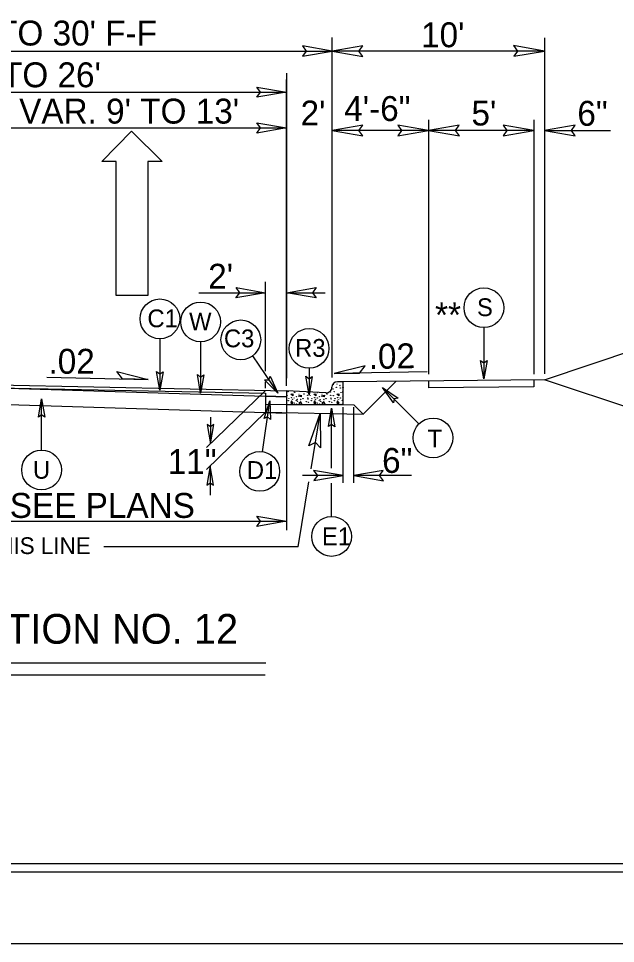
# Model space of a CAD drawing. Extents: x 958711 to 962106, y 831169 to 840840.
# Drawn here: x 959536.1 to 959723.1, y 834842.4 to 835132 of the extents above; entities that cross this region are included whole.
import ezdxf

# ---------------------------------------------------------------- set-up
doc = ezdxf.new("R2010")
doc.units = 0
for name, color, linetype in [('Old_Level_1', 7, 'Continuous'), ('Old_Level_11', 7, 'Continuous'), ('Old_Level_3', 7, 'Continuous'), ('Prop Dimension Text', 7, 'Continuous'), ('Prop Lane Arrow CELL', 7, 'Continuous'), ('Sheet Plot Border Inside CELL', 7, 'Continuous'), ('Sheet Plot Border Outside CELL', 7, 'Continuous'), ('Sheet Typical CELL', 7, 'Continuous'), ('Typical ID Circle CELL', 7, 'Continuous'), ('Typical Terminator CELL', 7, 'Continuous'), ('Typical Text ID Circle CELL', 7, 'Continuous')]:
    doc.layers.add(name, color=color, linetype=linetype)

# ---------------------------------------------------------------- blocks, each defined once
blk = doc.blocks.new('Lane Arrow Through')
at = {"layer": 'Prop Lane Arrow CELL'}
for p, q in [((-3.15, 1.6), (-3.15, 3.1)), ((-3.15, 3.1), (0, 0)), ((-17.15, 1.6), (-3.15, 1.6)), ((-17.15, -1.7), (-17.15, 1.6)), ((0, 0), (-3.15, -3.2)), ((-3.15, -1.7), (-17.15, -1.7)), ((-3.15, -3.2), (-3.15, -1.7))]:
    blk.add_line(p, q, dxfattribs=at)

msp = doc.modelspace()

# ---------------------------------------------------------------- linework, layer by layer
at = {"layer": 'Old_Level_1'}
for p, q in [((959634.32, 835019.58), (959634.32, 835126.05)), ((959700.88, 835126), (959700.88, 835020.79)), ((959418.82, 835121.85), (959634.32, 835121.85)), ((959700.88, 835121.85), (959634.32, 835121.85)), ((959620.02, 835114.91), (959620.02, 835019.44)), ((959620.02, 835016.99), (959620.02, 835112.9)), ((959433.06, 835108.99), (959620.02, 835108.99)), ((959664.55, 835100.29), (959664.55, 835020.64)), ((959697.57, 835100.29), (959697.57, 835020.72)), ((959526.54, 835097.75), (959620.02, 835097.75)), ((959664.55, 835096.97), (959634.32, 835096.97)), ((959697.57, 835096.97), (959664.55, 835096.97)), ((959700.88, 835096.97), (959721.54, 835096.97)), ((959613.48, 835021.65), (959613.48, 835049.62)), ((959592.56, 835046.17), (959613.48, 835046.17)), ((959620.08, 835046.17), (959632.2, 835046.17)), ((959700.88, 835018.94), (959778.06, 835044.67)), ((959664.16, 835021.44), (959634.95, 835020.85)), ((959526.54, 835017.35), (959620.02, 835015.46)), ((959544.97, 835019.69), (959576.67, 835019.05)), ((959613.48, 835016.33), (959613.48, 835018.23)), ((959700.88, 835018.94), (959637.83, 835018.31)), ((959644.1, 835008.14), (959654.42, 835018.47)), ((959664.55, 835018.57), (959664.55, 835016.39)), ((959697.57, 835018.9), (959697.57, 835016.72)), ((959778.06, 834993.21), (959700.88, 835018.94)), ((959526.53, 835016.48), (959613.48, 835014.73)), ((959526.57, 835016.48), (959620.02, 835013.55)), ((959613.48, 835015.59), (959595.01, 834997.66)), ((959613.48, 835014.73), (959613.48, 835008.76)), ((959697.57, 835016.72), (959664.55, 835016.39)), ((959526.54, 835011.35), (959620.02, 835008.42)), ((959613.48, 835013.86), (959620.02, 835013.73)), ((959613.48, 835011.31), (959620.02, 835011.18)), ((959620.02, 835013.55), (959620.02, 835008.42)), ((959637.83, 835011.18), (959641.13, 835011.11)), ((959641.13, 835011.11), (959644.1, 835008.14)), ((959613.46, 835008.76), (959594.98, 834990.84)), ((959613.46, 835008.76), (959644.1, 835008.14)), ((959620.02, 835008.23), (959620.02, 834971.78)), ((959627.75, 834990.99), (959630.62, 835008.4)), ((959637.83, 834986.62), (959637.83, 835010.38)), ((959641.13, 834986.62), (959641.13, 835010.38)), ((959596.22, 835007.2), (959596.22, 834998.84)), ((959596.16, 834992.01), (959596.15, 834982.79)), ((959637.83, 834988.92), (959625.06, 834988.92)), ((959659.27, 834988.92), (959641.13, 834988.92)), ((959623.73, 834966.64), (959627.08, 834986.98)), ((959433.06, 834974.66), (959620.02, 834974.66)), ((959623.73, 834966.64), (959562.82, 834966.64)), ((959613.61, 834930.23), (959445.91, 834930.23)), ((959613.32, 834926.42), (959445.63, 834926.42))]:
    msp.add_line(p, q, dxfattribs=at)
msp.add_arc((959637.52, 835014.72), 0.309, 0, 90, dxfattribs=at)
at = {"layer": 'Old_Level_11'}
for p, q in [((959644.68, 835023.27), (959634.95, 835020.85)), ((959642.95, 835021.01), (959644.68, 835023.27)), ((959568.67, 835019.21), (959566.94, 835021.47)), ((959566.94, 835021.47), (959576.67, 835019.05)), ((959634.95, 835020.85), (959642.95, 835021.01)), ((959576.67, 835019.05), (959568.67, 835019.21))]:
    msp.add_line(p, q, dxfattribs=at)
for points in [[(959643.93, 835123.51), (959634.32, 835121.85), (959643.99, 835120.14), (959642.76, 835121.85)], [(959691.27, 835120.2), (959700.88, 835121.85), (959691.21, 835123.56), (959692.44, 835121.85)], [(959643.93, 835098.62), (959634.32, 835096.97), (959643.99, 835095.25), (959642.76, 835096.97)], [(959654.95, 835095.31), (959664.55, 835096.97), (959654.89, 835098.67), (959656.12, 835096.97)], [(959674.16, 835098.62), (959664.55, 835096.97), (959674.22, 835095.25), (959672.99, 835096.97)], [(959687.97, 835095.31), (959697.57, 835096.97), (959687.91, 835098.67), (959689.14, 835096.97)], [(959710.48, 835098.62), (959700.88, 835096.97), (959710.54, 835095.25), (959709.31, 835096.97)], [(959627.1, 834998.27), (959630.62, 835008.4), (959630.74, 834997.61), (959629.11, 834999.25)]]:
    msp.add_lwpolyline(points, close=True, dxfattribs=at)
at = {"layer": 'Old_Level_3'}
for p, q in [((959637.52, 835018.31), (959636.04, 835018.31)), ((959637.83, 835014.74), (959637.83, 835018)), ((959632.42, 835014.84), (959620.02, 835015.46)), ((959620.02, 835015.46), (959620.02, 835011.18)), ((959621.38, 835014.46), (959622, 835014.49)), ((959622, 835013.87), (959621.38, 835014.46)), ((959622, 835014.49), (959622, 835013.87)), ((959623.81, 835013.81), (959624.7, 835014.06)), ((959624.7, 835014.06), (959624.6, 835013.54)), ((959628.6, 835014.46), (959629.23, 835014.49)), ((959629.23, 835013.87), (959628.6, 835014.46)), ((959629.23, 835014.49), (959629.23, 835013.87)), ((959631.04, 835013.81), (959631.93, 835014.06)), ((959631.93, 835014.06), (959631.83, 835013.54)), ((959632.42, 835014.84), (959632.42, 835014.84)), ((959634.24, 835015.95), (959634.08, 835015.99)), ((959634.12, 835016.11), (959634.24, 835015.95)), ((959635.83, 835014.46), (959636.46, 835014.49)), ((959636.46, 835013.87), (959635.83, 835014.46)), ((959636.46, 835014.49), (959636.46, 835013.87)), ((959637.83, 835011.18), (959637.83, 835014.74)), ((959620.02, 835011.18), (959637.83, 835011.18)), ((959621.6, 835012.29), (959621.41, 835011.63)), ((959621.41, 835011.63), (959622.1, 835011.59)), ((959622.1, 835011.59), (959621.6, 835012.29)), ((959624.6, 835013.54), (959623.81, 835013.81)), ((959624.54, 835011.96), (959623.94, 835011.53)), ((959623.94, 835011.53), (959624.9, 835011.3)), ((959624.9, 835011.3), (959624.54, 835011.96)), ((959628.83, 835012.29), (959628.64, 835011.63)), ((959628.64, 835011.63), (959629.32, 835011.59)), ((959629.32, 835011.59), (959628.83, 835012.29)), ((959631.83, 835013.54), (959631.04, 835013.81)), ((959631.77, 835011.96), (959631.17, 835011.53)), ((959631.17, 835011.53), (959632.13, 835011.3)), ((959632.13, 835011.3), (959631.77, 835011.96)), ((959636.05, 835012.29), (959635.87, 835011.63)), ((959635.87, 835011.63), (959636.55, 835011.59)), ((959636.55, 835011.59), (959636.05, 835012.29))]:
    msp.add_line(p, q, dxfattribs=at)
for centre in [(959634.67, 835017.4), (959635.86, 835017.54), (959636.78, 835017.14), (959620.25, 835013.97), (959620.54, 835015.16), (959622.63, 835014.96), (959623.97, 835014.3), (959625.52, 835014.46), (959626.68, 835014.03), (959627.47, 835013.97), (959631.2, 835014.3), (959632.75, 835014.46), (959633.81, 835015.12), (959633.91, 835014.03), (959634.63, 835016.02), (959634.7, 835013.97), (959635, 835015.16), (959635.69, 835016.54), (959636.95, 835016.35), (959637.08, 835014.96), (959637.76, 835016.44), (959620.61, 835012.39), (959620.78, 835012.98), (959621.63, 835013.34), (959621.9, 835012.75), (959622.46, 835013.24), (959622.63, 835011.59), (959623.09, 835012.52), (959623.18, 835011.33), (959623.21, 835013.67), (959623.41, 835012.72), (959623.51, 835012.16), (959624.53, 835012.72), (959625.23, 835013.01), (959626.25, 835012.06), (959626.71, 835013.17), (959626.81, 835012.88), (959626.98, 835011.89), (959627.84, 835012.39), (959628, 835012.98), (959628.86, 835013.34), (959629.13, 835012.75), (959629.69, 835013.24), (959629.85, 835011.59), (959630.32, 835012.52), (959630.41, 835011.33), (959630.44, 835013.67), (959630.64, 835012.72), (959630.74, 835012.16), (959631.76, 835012.72), (959632.45, 835013.01), (959633.48, 835012.06), (959633.94, 835013.17), (959634.04, 835012.88), (959634.21, 835011.89), (959635.06, 835012.39), (959635.23, 835012.98), (959636.09, 835013.34), (959636.35, 835012.75), (959636.91, 835013.24), (959637.08, 835011.59), (959637.54, 835012.52), (959637.63, 835011.33), (959637.67, 835013.67)]:
    msp.add_circle(centre, 0.0464, dxfattribs=at)
for centre, radius, start, end in [((959636.04, 835016.53), 1.78, 90, 178.9266), ((959637.52, 835018), 0.309, 0, 90), ((959637.63, 835018.23), 0.0464, 169.6531, 280.3469), ((959626.58, 835015.12), 0.0464, 164.1199, 10.1626), ((959629.85, 835014.96), 0.0464, 162.062, 12.2205), ((959632.51, 835016.6), 1.76, 267.1376, 358.9266), ((959637.86, 835012.72), 0.0464, 150.4173, 209.5827)]:
    msp.add_arc(centre, radius, start, end, dxfattribs=at)
at = {"layer": 'Sheet Plot Border Inside CELL'}
msp.add_lwpolyline([(960390.3, 835919.97), (958723.8, 835919.97), (958723.8, 834864.87), (960390.3, 834864.87)], close=True, dxfattribs=at)
at = {"layer": 'Sheet Plot Border Outside CELL'}
msp.add_lwpolyline([(960394.8, 835942.42), (958710.8, 835942.42), (958710.8, 834842.42), (960394.8, 834842.42)], close=True, dxfattribs=at)
at = {"layer": 'Sheet Typical CELL'}
msp.add_lwpolyline([(960377.8, 835917.42), (958877.8, 835917.42), (958877.8, 834867.42), (960377.8, 834867.42)], close=True, dxfattribs=at)
at = {"layer": 'Typical ID Circle CELL'}
for p, q in [((959681.91, 835035.24), (959681.91, 835019.16)), ((959580.39, 835031.76), (959580.39, 835015.68)), ((959593.14, 835030.81), (959593.14, 835014.72)), ((959609.38, 835026.36), (959617.32, 835014.71)), ((959627.14, 835022.5), (959627.14, 835014.2)), ((959661.56, 835005.11), (959650.18, 835016.49)), ((959543.31, 834996.91), (959543.31, 835012.99)), ((959612.56, 834996.39), (959614.83, 835012.31)), ((959634.2, 834991.25), (959634.2, 835010.02)), ((959634.2, 834976.08), (959634.2, 834986.58))]:
    msp.add_line(p, q, dxfattribs=at)
for centre in [(959681.91, 835041.47), (959580.39, 835037.99), (959593.14, 835037.03), (959605.74, 835031.41), (959627.14, 835028.73), (959665.96, 835000.71), (959543.31, 834990.68), (959611.68, 834990.23), (959634.2, 834969.86)]:
    msp.add_circle(centre, 6.23, dxfattribs=at)
at = {"layer": 'Typical Terminator CELL'}
for points in [[(959625.1, 835120.26), (959634.32, 835121.85), (959625.05, 835123.49), (959626.23, 835121.85)], [(959610.8, 835110.58), (959620.02, 835108.99), (959610.75, 835107.35), (959611.93, 835108.99)], [(959610.8, 835099.34), (959620.02, 835097.75), (959610.75, 835096.11), (959611.93, 835097.75)], [(959604.26, 835047.76), (959613.48, 835046.17), (959604.21, 835044.53), (959605.39, 835046.17)], [(959629.31, 835044.58), (959620.08, 835046.17), (959629.36, 835047.81), (959628.18, 835046.17)], [(959682.9, 835024.92), (959681.91, 835019.16), (959680.88, 835024.95), (959681.91, 835024.21)], [(959581.38, 835021.44), (959580.39, 835015.68), (959579.36, 835021.47), (959580.39, 835020.74)], [(959594.13, 835020.49), (959593.14, 835014.72), (959592.12, 835020.52), (959593.14, 835019.78)], [(959614.89, 835020.03), (959617.32, 835014.71), (959613.2, 835018.92), (959614.47, 835018.89)], [(959628.13, 835019.97), (959627.14, 835014.2), (959626.12, 835020), (959627.14, 835019.26)], [(959653.55, 835011.71), (959650.18, 835016.49), (959655, 835013.11), (959653.76, 835012.91)], [(959542.32, 835007.23), (959543.31, 835012.99), (959544.34, 835007.2), (959543.31, 835007.93)], [(959613.03, 835006.75), (959614.83, 835012.31), (959615.03, 835006.43), (959614.12, 835007.3)], [(959633.21, 835004.26), (959634.2, 835010.02), (959635.23, 835004.23), (959634.2, 835004.96)], [(959595.17, 835004.9), (959596.22, 834998.84), (959597.3, 835004.94), (959596.22, 835004.16)], [(959597.2, 834985.95), (959596.16, 834992.01), (959595.08, 834985.91), (959596.15, 834986.69)], [(959628.6, 834987.33), (959637.83, 834988.92), (959628.55, 834990.56), (959629.73, 834988.92)], [(959650.35, 834990.51), (959641.13, 834988.92), (959650.4, 834987.28), (959649.22, 834988.92)], [(959610.8, 834976.25), (959620.02, 834974.66), (959610.75, 834973.02), (959611.93, 834974.66)]]:
    msp.add_lwpolyline(points, close=True, dxfattribs=at)

# ---------------------------------------------------------------- block references
at = {"layer": 'Old_Level_1', "xscale": 3, "yscale": 3, "rotation": 89.99999999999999}
msp.add_blockref('Lane Arrow Through', (959571.5, 835096.75), dxfattribs=at)

# ---------------------------------------------------------------- texts
at = {"layer": 'Old_Level_1'}
for s, height, p in [("VAR. 22' F-F TO 30' F-F", 7.8009, (959466.52, 835123.57)), ('GRADE TO THIS LINE', 5.2473, (959486.56, 834964.35)), ('TYPICAL SECTION NO. 12', 9.3239, (959451.08, 834936.27))]:
    msp.add_text(s, height=height, dxfattribs=at).set_placement(p)
at = {"layer": 'Old_Level_11'}
msp.add_text('11"', height=7.801, dxfattribs=at).set_placement((959582.84, 834989.39))
at = {"layer": 'Old_Level_3'}
for s, p in [("10'", (959662.22, 835123.03)), ('4\'-6"', (959638.14, 835099.93)), ("2'", (959624.47, 835098.53)), ("5'", (959678.01, 835098.53)), ('6"', (959711.19, 835098.44))]:
    msp.add_text(s, height=7.801, dxfattribs=at).set_placement(p)
at = {"layer": 'Prop Dimension Text'}
for s, height, rotation, p in [("VAR. 18' TO 26'", 7.8009, 0, (959487.18, 835110.5)), ("VAR. 9' TO 13'", 7.8009, 0, (959536.29, 835099.13)), ("2'", 7.801, 0, (959595.52, 835047.42)), ('**', 7.801, 0, (959666.61, 835035.32)), ('.02', 7.801, 360, (959545.48, 835020.8)), ('.02', 7.801, 1.1839, (959645.89, 835022.27)), ('6"', 7.801, 0, (959650.01, 834989.76)), ('VAR. WIDTH SEE PLANS', 7.8009, 0, (959469.03, 834975.67))]:
    msp.add_text(s, height=height, rotation=rotation, dxfattribs=at).set_placement(p)
at = {"layer": 'Typical Text ID Circle CELL'}
for s, height, p in [('S', 5.57, (959679.74, 835038.84)), ('C1', 5.572, (959576.48, 835035.36)), ('W', 5.57, (959589.53, 835034.4)), ('C3', 5.572, (959600.45, 835029.09)), ('R3', 5.572, (959622.76, 835026.1)), ('T', 5.57, (959664.25, 834997.73)), ('U', 5.57, (959540.61, 834987.94)), ('D1', 5.572, (959607.64, 834987.87)), ('E1', 5.572, (959631.17, 834967.12))]:
    msp.add_text(s, height=height, dxfattribs=at).set_placement(p)

doc.saveas('drawing.dxf')
